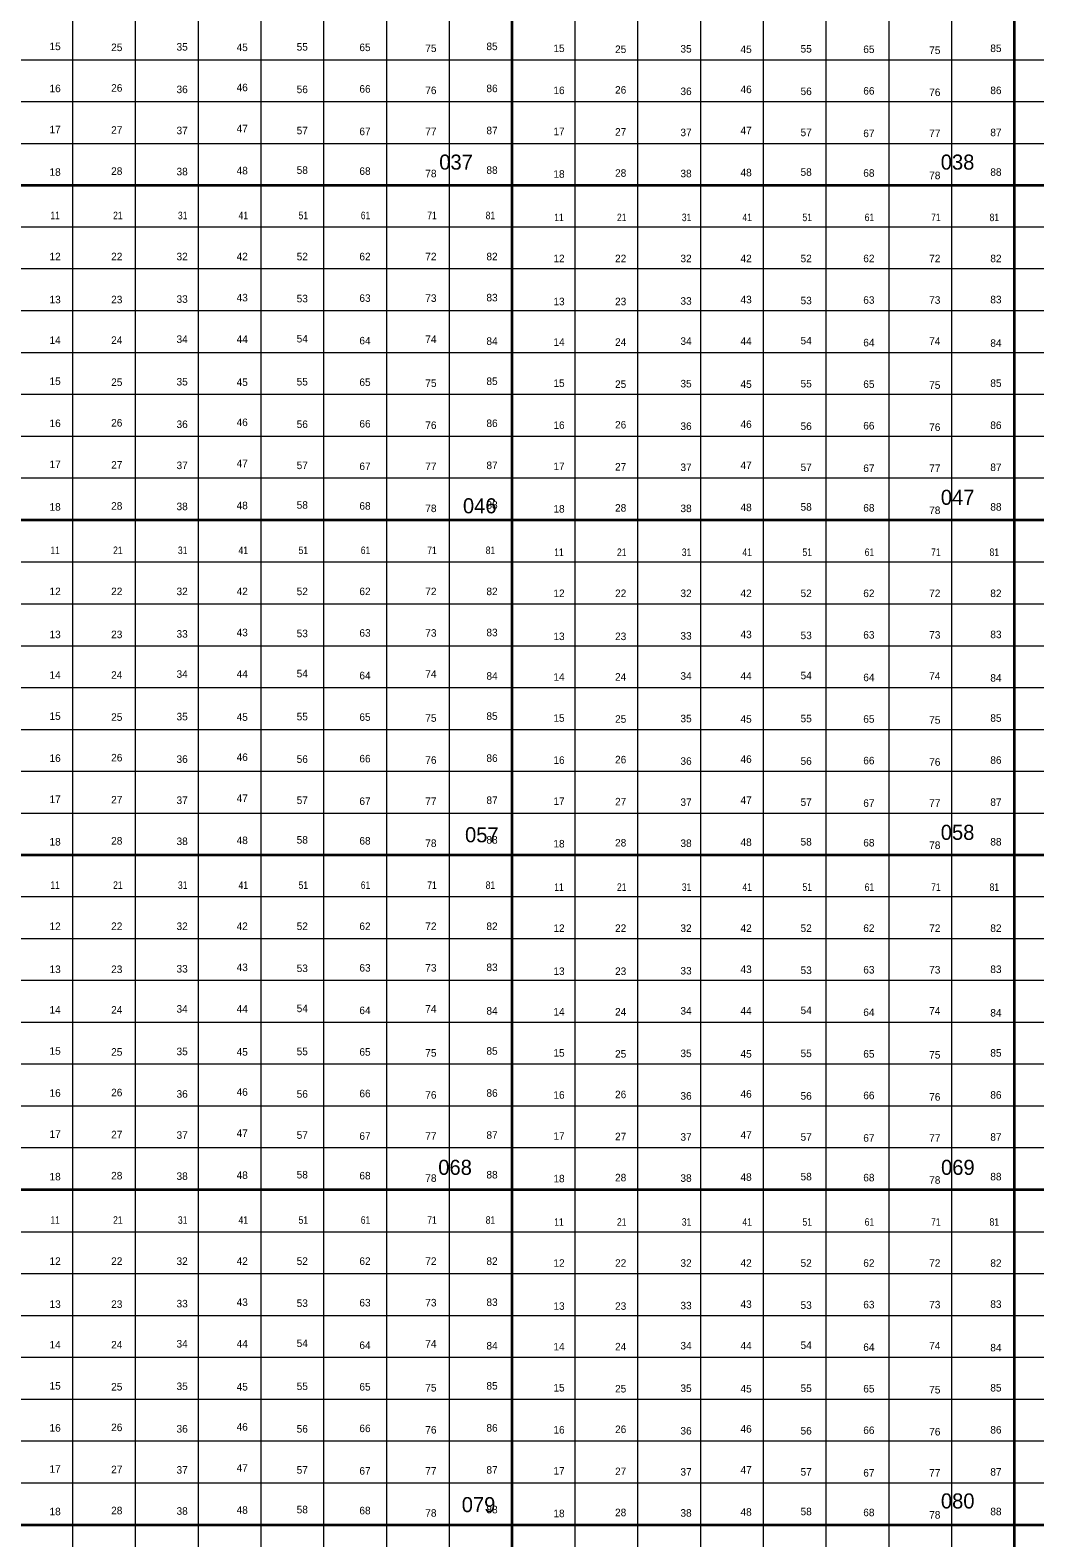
# Model space of a CAD drawing. Extents: x 639000 to 672000, y 222000 to 252000.
# Drawn here: x 654120 to 660121, y 233921 to 242926 of the extents above; entities that cross this region are included whole.
import ezdxf
from ezdxf.enums import TextEntityAlignment as Align

# ---------------------------------------------------------------- set-up
doc = ezdxf.new("R2010")
doc.units = 0
doc.header["$LTSCALE"] = 18
doc.layers.add('1', color=7, linetype='Continuous', lineweight=13)
doc.layers.add('2', color=7, linetype='Continuous')
doc.layers.add('29', color=7, linetype='Continuous')

msp = doc.modelspace()

# ---------------------------------------------------------------- linework, layer by layer
at = {"layer": '1'}
for p, q in [((654375, 222000), (654375, 252000)), ((654750, 222000), (654750, 252000)), ((655125, 222000), (655125, 252000)), ((655500, 222000), (655500, 252000)), ((655875, 222000), (655875, 252000)), ((656250, 222000), (656250, 252000)), ((656625, 222000), (656625, 252000)), ((657375, 222000), (657375, 248000)), ((657750, 222000), (657750, 248000)), ((658125, 222000), (658125, 248000)), ((658500, 222000), (658500, 248000)), ((658875, 222000), (658875, 248000)), ((659250, 222000), (659250, 248000)), ((659625, 222000), (659625, 248000)), ((639000, 242750), (666000, 242750)), ((639000, 242500), (666000, 242500)), ((639000, 242250), (666000, 242250)), ((672000, 241750), (639000, 241750)), ((672000, 241500), (639000, 241500)), ((672000, 241250), (639000, 241250)), ((672000, 241000), (639000, 241000)), ((672000, 240750), (639000, 240750)), ((672000, 240500), (639000, 240500)), ((672000, 240250), (639000, 240250)), ((639000, 239750), (672000, 239750)), ((639000, 239500), (672000, 239500)), ((639000, 239250), (672000, 239250)), ((639000, 239000), (672000, 239000)), ((639000, 238750), (672000, 238750)), ((639000, 238500), (672000, 238500)), ((639000, 238250), (672000, 238250)), ((672000, 237750), (639000, 237750)), ((672000, 237500), (639000, 237500)), ((672000, 237250), (639000, 237250)), ((672000, 237000), (639000, 237000)), ((672000, 236750), (639000, 236750)), ((672000, 236500), (639000, 236500)), ((672000, 236250), (639000, 236250)), ((639000, 235750), (672000, 235750)), ((639000, 235500), (672000, 235500)), ((639000, 235250), (672000, 235250)), ((639000, 235000), (672000, 235000)), ((639000, 234750), (672000, 234750)), ((639000, 234500), (672000, 234500)), ((639000, 234250), (672000, 234250))]:
    msp.add_line(p, q, dxfattribs=at)
at = {"layer": '1', "lineweight": 35}
for p, q in [((657000, 222000), (657000, 252000)), ((660000, 222000), (660000, 248000)), ((639000, 242000), (672000, 242000)), ((672000, 240000), (639000, 240000)), ((639000, 238000), (672000, 238000)), ((672000, 236000), (639000, 236000)), ((639000, 234000), (672000, 234000))]:
    msp.add_line(p, q, dxfattribs=at)

# ---------------------------------------------------------------- texts
at = {"layer": '2'}
for s, p in [('037', (656663.86, 242093.33)), ('038', (659659.19, 242093.33)), ('047', (659659.59, 240091.12)), ('046', (656805.39, 240040.61)), ('058', (659659.19, 238090.28)), ('057', (656817.9, 238075.75)), ('068', (656657.97, 236089.44)), ('069', (659660.83, 236089.44)), ('079', (656798.21, 234074.94)), ('080', (659660.01, 234096.83))]:
    msp.add_text(s, height=90, rotation=359.94, dxfattribs=at).set_placement(p, align=Align.CENTER)
at = {"layer": '29'}
for s, p in [('15', (654269.27, 242806.98)), ('25', (654637.53, 242801.21)), ('35', (655028, 242804.1)), ('45', (655386.73, 242801.21)), ('55', (655745.46, 242804.1)), ('65', (656120.07, 242801.21)), ('75', (656513.72, 242795.44)), ('85', (656878.8, 242806.99)), ('15', (657278.8, 242795.44)), ('25', (657647.05, 242789.66)), ('35', (658037.53, 242792.55)), ('45', (658396.26, 242789.66)), ('55', (658754.99, 242792.55)), ('65', (659129.59, 242789.66)), ('75', (659523.24, 242783.89)), ('85', (659888.33, 242795.44)), ('16', (654269.27, 242555.82)), ('26', (654637.53, 242558.71)), ('36', (655028, 242550.05)), ('46', (655386.73, 242561.59)), ('56', (655745.46, 242550.05)), ('66', (656120.07, 242552.93)), ('86', (656878.8, 242555.82)), ('26', (657647.05, 242547.16)), ('46', (658396.26, 242550.05)), ('76', (656513.72, 242544.27)), ('16', (657278.8, 242544.27)), ('36', (658037.53, 242538.5)), ('56', (658754.99, 242538.5)), ('66', (659129.59, 242541.39)), ('76', (659523.24, 242532.72)), ('86', (659888.33, 242544.27)), ('17', (654269.27, 242310.43)), ('27', (654637.53, 242307.54)), ('37', (655028, 242304.66)), ('47', (655386.73, 242316.2)), ('57', (655745.46, 242304.66)), ('67', (656120.07, 242298.88)), ('77', (656513.72, 242298.88)), ('87', (656878.8, 242304.66)), ('17', (657278.8, 242298.88)), ('27', (657647.05, 242295.99)), ('37', (658037.53, 242293.11)), ('47', (658396.26, 242304.65)), ('57', (658754.99, 242293.11)), ('67', (659129.59, 242287.33)), ('77', (659523.25, 242287.33)), ('87', (659888.33, 242293.11)), ('18', (654269.27, 242056.38)), ('28', (654637.53, 242062.15)), ('38', (655028, 242059.27)), ('48', (655386.73, 242065.04)), ('58', (655745.46, 242067.93)), ('68', (656120.07, 242062.15)), ('78', (656513.72, 242047.72)), ('88', (656878.8, 242067.93)), ('18', (657278.8, 242044.83)), ('28', (657647.05, 242050.6)), ('38', (658037.53, 242047.72)), ('48', (658396.26, 242053.49)), ('58', (658754.99, 242056.38)), ('68', (659129.59, 242050.6)), ('78', (659523.24, 242036.17)), ('88', (659888.32, 242056.38)), ('12', (654269.27, 241551.82)), ('22', (654637.53, 241551.82)), ('32', (655028, 241551.82)), ('42', (655386.73, 241551.82)), ('52', (655745.46, 241551.82)), ('62', (656120.07, 241551.82)), ('72', (656513.72, 241551.82)), ('82', (656878.8, 241551.82)), ('12', (657278.8, 241540.27)), ('22', (657647.05, 241540.27)), ('32', (658037.53, 241540.27)), ('42', (658396.26, 241540.27)), ('52', (658754.99, 241540.27)), ('62', (659129.59, 241540.27)), ('72', (659523.24, 241540.27)), ('82', (659888.32, 241540.27)), ('13', (654269.27, 241294.88)), ('23', (654637.53, 241294.88)), ('33', (655028, 241297.77)), ('43', (655386.73, 241306.43)), ('53', (655745.46, 241300.65)), ('63', (656120.07, 241303.54)), ('73', (656513.72, 241303.54)), ('83', (656878.8, 241306.43)), ('33', (658037.53, 241286.22)), ('43', (658396.26, 241294.88)), ('53', (658754.99, 241289.11)), ('63', (659129.59, 241291.99)), ('73', (659523.24, 241291.99)), ('83', (659888.33, 241294.88)), ('13', (657278.8, 241283.33)), ('23', (657647.05, 241283.33)), ('14', (654269.27, 241052.38)), ('24', (654637.53, 241052.38)), ('34', (655028, 241058.15)), ('44', (655386.73, 241058.15)), ('54', (655745.46, 241061.04)), ('64', (656120.07, 241049.49)), ('74', (656513.72, 241058.15)), ('84', (656878.8, 241046.6)), ('14', (657278.8, 241040.83)), ('24', (657647.05, 241040.83)), ('34', (658037.53, 241046.6)), ('44', (658396.26, 241046.6)), ('54', (658754.99, 241049.49)), ('64', (659129.59, 241037.94)), ('74', (659523.24, 241046.6)), ('84', (659888.33, 241035.05)), ('15', (654269.27, 240806.98)), ('25', (654637.53, 240801.21)), ('35', (655028, 240804.1)), ('45', (655386.73, 240801.21)), ('55', (655745.46, 240804.1)), ('65', (656120.07, 240801.21)), ('75', (656513.72, 240795.44)), ('85', (656878.8, 240806.99)), ('15', (657278.8, 240795.44)), ('25', (657647.05, 240789.66)), ('35', (658037.53, 240792.55)), ('45', (658396.26, 240789.66)), ('55', (658754.99, 240792.55)), ('65', (659129.59, 240789.66)), ('75', (659523.24, 240783.89)), ('85', (659888.33, 240795.44)), ('16', (654269.27, 240555.82)), ('26', (654637.53, 240558.71)), ('36', (655028, 240550.05)), ('46', (655386.73, 240561.59)), ('56', (655745.46, 240550.05)), ('66', (656120.07, 240552.93)), ('76', (656513.72, 240544.27)), ('86', (656878.8, 240555.82)), ('16', (657278.8, 240544.27)), ('26', (657647.05, 240547.16)), ('36', (658037.53, 240538.5)), ('46', (658396.26, 240550.05)), ('56', (658754.99, 240538.5)), ('66', (659129.59, 240541.39)), ('76', (659523.24, 240532.72)), ('86', (659888.33, 240544.27)), ('17', (654269.27, 240310.43)), ('27', (654637.53, 240307.54)), ('37', (655028, 240304.66)), ('47', (655386.73, 240316.2)), ('57', (655745.46, 240304.66)), ('67', (656120.07, 240298.88)), ('77', (656513.72, 240298.88)), ('87', (656878.8, 240304.66)), ('17', (657278.8, 240298.88)), ('27', (657647.05, 240295.99)), ('47', (658396.26, 240304.65)), ('37', (658037.53, 240293.11)), ('57', (658754.99, 240293.11)), ('67', (659129.59, 240287.33)), ('77', (659523.25, 240287.33)), ('87', (659888.33, 240293.11)), ('18', (654269.27, 240056.38)), ('28', (654637.53, 240062.15)), ('38', (655028, 240059.27)), ('48', (655386.73, 240065.04)), ('58', (655745.46, 240067.93)), ('68', (656120.07, 240062.15)), ('78', (656513.72, 240047.72)), ('88', (656878.8, 240067.93)), ('18', (657278.8, 240044.83)), ('28', (657647.05, 240050.6)), ('38', (658037.53, 240047.72)), ('48', (658396.26, 240053.49)), ('58', (658754.99, 240056.38)), ('68', (659129.59, 240050.6)), ('78', (659523.24, 240036.17)), ('88', (659888.32, 240056.38)), ('12', (654269.27, 239551.82)), ('22', (654637.53, 239551.82)), ('32', (655028, 239551.82)), ('42', (655386.73, 239551.82)), ('52', (655745.46, 239551.82)), ('62', (656120.07, 239551.82)), ('72', (656513.72, 239551.82)), ('82', (656878.8, 239551.82)), ('12', (657278.8, 239540.27)), ('22', (657647.05, 239540.27)), ('32', (658037.53, 239540.27)), ('42', (658396.26, 239540.27)), ('52', (658754.99, 239540.27)), ('62', (659129.59, 239540.27)), ('72', (659523.24, 239540.27)), ('82', (659888.32, 239540.27)), ('43', (655386.73, 239306.43)), ('83', (656878.8, 239306.43)), ('13', (654269.27, 239294.88)), ('23', (654637.53, 239294.88)), ('33', (655028, 239297.77)), ('53', (655745.46, 239300.65)), ('63', (656120.07, 239303.54)), ('73', (656513.72, 239303.54)), ('13', (657278.8, 239283.33)), ('23', (657647.05, 239283.33)), ('33', (658037.53, 239286.22)), ('43', (658396.26, 239294.88)), ('53', (658754.99, 239289.11)), ('63', (659129.59, 239291.99)), ('73', (659523.24, 239291.99)), ('83', (659888.33, 239294.88)), ('14', (654269.27, 239052.38)), ('24', (654637.53, 239052.38)), ('34', (655028, 239058.15)), ('44', (655386.73, 239058.15)), ('54', (655745.46, 239061.04)), ('64', (656120.07, 239049.49)), ('74', (656513.72, 239058.15)), ('84', (656878.8, 239046.6)), ('14', (657278.8, 239040.83)), ('24', (657647.05, 239040.83)), ('34', (658037.53, 239046.6)), ('44', (658396.26, 239046.6)), ('54', (658754.99, 239049.49)), ('64', (659129.59, 239037.94)), ('74', (659523.24, 239046.6)), ('84', (659888.33, 239035.05)), ('15', (654269.27, 238806.98)), ('25', (654637.53, 238801.21)), ('35', (655028, 238804.1)), ('45', (655386.73, 238801.21)), ('55', (655745.46, 238804.1)), ('65', (656120.07, 238801.21)), ('75', (656513.72, 238795.44)), ('85', (656878.8, 238806.99)), ('15', (657278.8, 238795.44)), ('25', (657647.05, 238789.66)), ('35', (658037.53, 238792.55)), ('45', (658396.26, 238789.66)), ('55', (658754.99, 238792.55)), ('65', (659129.59, 238789.66)), ('75', (659523.24, 238783.89)), ('85', (659888.33, 238795.44)), ('16', (654269.27, 238555.82)), ('26', (654637.53, 238558.71)), ('36', (655028, 238550.05)), ('46', (655386.73, 238561.59)), ('56', (655745.46, 238550.05)), ('66', (656120.07, 238552.93)), ('76', (656513.72, 238544.27)), ('86', (656878.8, 238555.82)), ('16', (657278.8, 238544.27)), ('26', (657647.05, 238547.16)), ('36', (658037.53, 238538.5)), ('46', (658396.26, 238550.05)), ('56', (658754.99, 238538.5)), ('66', (659129.59, 238541.39)), ('76', (659523.24, 238532.72)), ('86', (659888.33, 238544.27)), ('47', (655386.73, 238316.2)), ('17', (654269.27, 238310.43)), ('27', (654637.53, 238307.54)), ('37', (655028, 238304.66)), ('57', (655745.46, 238304.66)), ('67', (656120.07, 238298.88)), ('77', (656513.72, 238298.88)), ('87', (656878.8, 238304.66)), ('17', (657278.8, 238298.88)), ('27', (657647.05, 238295.99)), ('37', (658037.53, 238293.11)), ('47', (658396.26, 238304.65)), ('57', (658754.99, 238293.11)), ('67', (659129.59, 238287.33)), ('77', (659523.25, 238287.33)), ('87', (659888.33, 238293.11)), ('18', (654269.27, 238056.38)), ('28', (654637.53, 238062.15)), ('38', (655028, 238059.27)), ('48', (655386.73, 238065.04)), ('58', (655745.46, 238067.93)), ('68', (656120.07, 238062.15)), ('78', (656513.72, 238047.72)), ('88', (656878.8, 238067.93)), ('18', (657278.8, 238044.83)), ('28', (657647.05, 238050.6)), ('38', (658037.53, 238047.72)), ('48', (658396.26, 238053.49)), ('58', (658754.99, 238056.38)), ('68', (659129.59, 238050.6)), ('88', (659888.32, 238056.38)), ('78', (659523.24, 238036.17)), ('12', (654269.27, 237551.82)), ('22', (654637.53, 237551.82)), ('32', (655028, 237551.82)), ('42', (655386.73, 237551.82)), ('52', (655745.46, 237551.82)), ('62', (656120.07, 237551.82)), ('72', (656513.72, 237551.82)), ('82', (656878.8, 237551.82)), ('12', (657278.8, 237540.27)), ('22', (657647.05, 237540.27)), ('32', (658037.53, 237540.27)), ('42', (658396.26, 237540.27)), ('52', (658754.99, 237540.27)), ('62', (659129.59, 237540.27)), ('72', (659523.24, 237540.27)), ('82', (659888.32, 237540.27)), ('13', (654269.27, 237294.88)), ('23', (654637.53, 237294.88)), ('33', (655028, 237297.77)), ('43', (655386.73, 237306.43)), ('53', (655745.46, 237300.65)), ('63', (656120.07, 237303.54)), ('73', (656513.72, 237303.54)), ('83', (656878.8, 237306.43)), ('13', (657278.8, 237283.33)), ('23', (657647.05, 237283.33)), ('33', (658037.53, 237286.22)), ('43', (658396.26, 237294.88)), ('53', (658754.99, 237289.11)), ('63', (659129.59, 237291.99)), ('73', (659523.24, 237291.99)), ('83', (659888.33, 237294.88)), ('34', (655028, 237058.15)), ('44', (655386.73, 237058.15)), ('54', (655745.46, 237061.04)), ('74', (656513.72, 237058.15)), ('14', (654269.27, 237052.38)), ('24', (654637.53, 237052.38)), ('64', (656120.07, 237049.49)), ('84', (656878.8, 237046.6)), ('14', (657278.8, 237040.83)), ('24', (657647.05, 237040.83)), ('34', (658037.53, 237046.6)), ('44', (658396.26, 237046.6)), ('54', (658754.99, 237049.49)), ('64', (659129.59, 237037.94)), ('74', (659523.24, 237046.6)), ('84', (659888.33, 237035.05)), ('15', (654269.27, 236806.98)), ('25', (654637.53, 236801.21)), ('35', (655028, 236804.1)), ('45', (655386.73, 236801.21)), ('55', (655745.46, 236804.1)), ('65', (656120.07, 236801.21)), ('75', (656513.72, 236795.44)), ('85', (656878.8, 236806.99)), ('15', (657278.8, 236795.44)), ('25', (657647.05, 236789.66)), ('35', (658037.53, 236792.55)), ('45', (658396.26, 236789.66)), ('55', (658754.99, 236792.55)), ('65', (659129.59, 236789.66)), ('75', (659523.24, 236783.89)), ('85', (659888.33, 236795.44)), ('16', (654269.27, 236555.82)), ('26', (654637.53, 236558.71)), ('36', (655028, 236550.05)), ('46', (655386.73, 236561.59)), ('56', (655745.46, 236550.05)), ('66', (656120.07, 236552.93)), ('76', (656513.72, 236544.27)), ('86', (656878.8, 236555.82)), ('16', (657278.8, 236544.27)), ('26', (657647.05, 236547.16)), ('36', (658037.53, 236538.5)), ('46', (658396.26, 236550.05)), ('56', (658754.99, 236538.5)), ('66', (659129.59, 236541.39)), ('76', (659523.24, 236532.72)), ('86', (659888.33, 236544.27)), ('17', (654269.27, 236310.43)), ('27', (654637.53, 236307.54)), ('37', (655028, 236304.66)), ('47', (655386.73, 236316.2)), ('57', (655745.46, 236304.66)), ('67', (656120.07, 236298.88)), ('77', (656513.72, 236298.88)), ('87', (656878.8, 236304.66)), ('17', (657278.8, 236298.88)), ('27', (657647.05, 236295.99)), ('37', (658037.53, 236293.11)), ('47', (658396.26, 236304.65)), ('57', (658754.99, 236293.11)), ('67', (659129.59, 236287.33)), ('77', (659523.25, 236287.33)), ('87', (659888.33, 236293.11)), ('48', (655386.73, 236065.04)), ('58', (655745.46, 236067.93)), ('88', (656878.8, 236067.93)), ('18', (654269.27, 236056.38)), ('28', (654637.53, 236062.15)), ('38', (655028, 236059.27)), ('68', (656120.07, 236062.15)), ('78', (656513.72, 236047.72)), ('18', (657278.8, 236044.83)), ('28', (657647.05, 236050.6)), ('38', (658037.53, 236047.72)), ('48', (658396.26, 236053.49)), ('58', (658754.99, 236056.38)), ('68', (659129.59, 236050.6)), ('78', (659523.24, 236036.17)), ('88', (659888.32, 236056.38)), ('12', (654269.27, 235551.82)), ('22', (654637.53, 235551.82)), ('32', (655028, 235551.82)), ('42', (655386.73, 235551.82)), ('52', (655745.46, 235551.82)), ('62', (656120.07, 235551.82)), ('72', (656513.72, 235551.82)), ('82', (656878.8, 235551.82)), ('12', (657278.8, 235540.27)), ('22', (657647.05, 235540.27)), ('32', (658037.53, 235540.27)), ('42', (658396.26, 235540.27)), ('52', (658754.99, 235540.27)), ('62', (659129.59, 235540.27)), ('72', (659523.24, 235540.27)), ('82', (659888.32, 235540.27)), ('13', (654269.27, 235294.88)), ('23', (654637.53, 235294.88)), ('33', (655028, 235297.77)), ('43', (655386.73, 235306.43)), ('53', (655745.46, 235300.65)), ('63', (656120.07, 235303.54)), ('73', (656513.72, 235303.54)), ('83', (656878.8, 235306.43)), ('13', (657278.8, 235283.33)), ('23', (657647.05, 235283.33)), ('33', (658037.53, 235286.22)), ('43', (658396.26, 235294.88)), ('53', (658754.99, 235289.11)), ('63', (659129.59, 235291.99)), ('73', (659523.24, 235291.99)), ('83', (659888.33, 235294.88)), ('14', (654269.27, 235052.38)), ('24', (654637.53, 235052.38)), ('34', (655028, 235058.15)), ('44', (655386.73, 235058.15)), ('54', (655745.46, 235061.04)), ('64', (656120.07, 235049.49)), ('74', (656513.72, 235058.15)), ('84', (656878.8, 235046.6)), ('14', (657278.8, 235040.83)), ('24', (657647.05, 235040.83)), ('34', (658037.53, 235046.6)), ('44', (658396.26, 235046.6)), ('54', (658754.99, 235049.49)), ('64', (659129.59, 235037.94)), ('74', (659523.24, 235046.6)), ('84', (659888.33, 235035.05)), ('15', (654269.27, 234806.98)), ('35', (655028, 234804.1)), ('55', (655745.46, 234804.1)), ('85', (656878.8, 234806.99)), ('25', (654637.53, 234801.21)), ('45', (655386.73, 234801.21)), ('65', (656120.07, 234801.21)), ('75', (656513.72, 234795.44)), ('15', (657278.8, 234795.44)), ('25', (657647.05, 234789.66)), ('35', (658037.53, 234792.55)), ('45', (658396.26, 234789.66)), ('55', (658754.99, 234792.55)), ('65', (659129.59, 234789.66)), ('75', (659523.24, 234783.89)), ('85', (659888.33, 234795.44)), ('16', (654269.27, 234555.82)), ('26', (654637.53, 234558.71)), ('36', (655028, 234550.05)), ('46', (655386.73, 234561.59)), ('56', (655745.46, 234550.05)), ('66', (656120.07, 234552.93)), ('76', (656513.72, 234544.27)), ('86', (656878.8, 234555.82)), ('16', (657278.8, 234544.27)), ('26', (657647.05, 234547.16)), ('36', (658037.53, 234538.5)), ('46', (658396.26, 234550.05)), ('56', (658754.99, 234538.5)), ('66', (659129.59, 234541.39)), ('76', (659523.24, 234532.72)), ('86', (659888.33, 234544.27)), ('17', (654269.27, 234310.43)), ('27', (654637.53, 234307.54)), ('37', (655028, 234304.66)), ('47', (655386.73, 234316.2)), ('57', (655745.46, 234304.66)), ('67', (656120.07, 234298.88)), ('77', (656513.72, 234298.88)), ('87', (656878.8, 234304.66)), ('17', (657278.8, 234298.88)), ('27', (657647.05, 234295.99)), ('37', (658037.53, 234293.11)), ('47', (658396.26, 234304.65)), ('57', (658754.99, 234293.11)), ('67', (659129.59, 234287.33)), ('77', (659523.25, 234287.33)), ('87', (659888.33, 234293.11)), ('18', (654269.27, 234056.38)), ('28', (654637.53, 234062.15)), ('38', (655028, 234059.27)), ('48', (655386.73, 234065.04)), ('58', (655745.46, 234067.93)), ('68', (656120.07, 234062.15)), ('78', (656513.72, 234047.72)), ('88', (656878.8, 234067.93)), ('18', (657278.8, 234044.83)), ('28', (657647.05, 234050.6)), ('38', (658037.53, 234047.72)), ('48', (658396.26, 234053.49)), ('58', (658754.99, 234056.38)), ('68', (659129.59, 234050.6)), ('78', (659523.24, 234036.17)), ('88', (659888.32, 234056.38))]:
    msp.add_text(s, height=45, dxfattribs=at).set_placement(p, align=Align.CENTER)
at = {"layer": '29', "width": 0.85}
for s, p in [('11', (654269.27, 241797.21)), ('21', (654643.88, 241797.21)), ('31', (655031.18, 241797.21)), ('41', (655393.08, 241797.21)), ('51', (655751.81, 241797.21)), ('61', (656123.24, 241797.21)), ('71', (656520.07, 241797.21)), ('81', (656869.28, 241797.21)), ('11', (657278.8, 241785.66)), ('21', (657653.4, 241785.66)), ('31', (658040.7, 241785.66)), ('41', (658402.61, 241785.66)), ('51', (658761.34, 241785.66)), ('61', (659132.77, 241785.66)), ('71', (659529.6, 241785.66)), ('81', (659878.8, 241785.66)), ('11', (654269.27, 239797.21)), ('21', (654643.88, 239797.21)), ('31', (655031.18, 239797.21)), ('41', (655393.08, 239797.21)), ('51', (655751.81, 239797.21)), ('61', (656123.24, 239797.21)), ('71', (656520.07, 239797.21)), ('81', (656869.28, 239797.21)), ('11', (657278.8, 239785.66)), ('21', (657653.4, 239785.66)), ('31', (658040.7, 239785.66)), ('41', (658402.61, 239785.66)), ('51', (658761.34, 239785.66)), ('61', (659132.77, 239785.66)), ('71', (659529.6, 239785.66)), ('81', (659878.8, 239785.66)), ('11', (654269.27, 237797.21)), ('21', (654643.88, 237797.21)), ('31', (655031.18, 237797.21)), ('41', (655393.08, 237797.21)), ('51', (655751.81, 237797.21)), ('61', (656123.24, 237797.21)), ('71', (656520.07, 237797.21)), ('81', (656869.28, 237797.21)), ('11', (657278.8, 237785.66)), ('21', (657653.4, 237785.66)), ('31', (658040.7, 237785.66)), ('41', (658402.61, 237785.66)), ('51', (658761.34, 237785.66)), ('61', (659132.77, 237785.66)), ('71', (659529.6, 237785.66)), ('81', (659878.8, 237785.66)), ('11', (654269.27, 235797.21)), ('21', (654643.88, 235797.21)), ('31', (655031.18, 235797.21)), ('41', (655393.08, 235797.21)), ('51', (655751.81, 235797.21)), ('61', (656123.24, 235797.21)), ('71', (656520.07, 235797.21)), ('81', (656869.28, 235797.21)), ('11', (657278.8, 235785.66)), ('21', (657653.4, 235785.66)), ('31', (658040.7, 235785.66)), ('41', (658402.61, 235785.66)), ('51', (658761.34, 235785.66)), ('61', (659132.77, 235785.66)), ('71', (659529.6, 235785.66)), ('81', (659878.8, 235785.66))]:
    msp.add_text(s, height=45, dxfattribs=at).set_placement(p, align=Align.CENTER)

doc.saveas('drawing.dxf')
